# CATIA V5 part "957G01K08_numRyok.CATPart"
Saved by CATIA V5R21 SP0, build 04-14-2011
Part number: 957G01K08_numRyok
Bounding box of the stored display mesh (mm): x -33.75 to 33.05, y -126.3 to -25.1, z -8 to 12
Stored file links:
  C:\Users\ALI OZGUN\Desktop\alhan\957G01K08_numRyok.CATPart
  C:\Users\ALI OZGUN\Desktop\alhan\960B01P01.CATPart
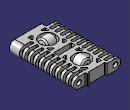
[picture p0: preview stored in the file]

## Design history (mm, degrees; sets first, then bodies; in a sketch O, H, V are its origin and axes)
Set1
  Plane1: type Normal, Curve Sketch12, RefPoint Sketch12.P3
  Point1: type Center, Curve edge [face of Pad1 from Sketch1.L2 | face of Pocket3 from Sketch4.A1]
  Line1: type PtDir, RefPoint Point1, Direction face of Pad1 from Sketch1.L2, Start 0, End 20
Set2
  Plane2: stored without definition
  Point2: stored without definition
  Line2: stored without definition
Body1 (main body)
  Sketch1 on zx-plane, origin (0, 0, 0), H (-1, 0, 0), V (0, 0, 1)
    construction line L1 (-25.05, 0) -> (25.75, 0)
    point P1 (-25.05, 0)
    line L2 (-25.05, 8) -> (25.75, 8)
    line L3 (25.75, -8) -> (-25.05, -8)
    arc A1 centre (25.75, 0) radius 8 from (25.75, 8) to (25.75, -8) cw
    arc A2 centre (-25.05, 0) radius 8 from (-25.05, -8) to (-25.05, 8) cw
    distance L1 L2 = 8
    distance P1 V = 25.05
    length L1 = 50.8
    coincidence: P1 H
    horizontal: L1 H
    tangency: A1 L2, A2 L2, A1 L3, A2 L3
  Pad1: profile Sketch1, direction (0, 1, 0), length 127.5, mirrored extent
  Sketch2 on face of Pad1 from Sketch1.L2, origin (0, 0, 8), H (1, 0, 0), V (0, 1, 0)
    line L1 (-50.9731, -119.3) -> (-16.75, -119.3)
    line L2 (-15.75, -120.3) -> (-15.75, -122.5)
    line L3 (-16.75, -123.5) -> (-50.9731, -123.5)
    line L4 (-50.9731, -123.5) -> (-50.9731, -119.3)
    arc A1 centre (-16.75, -120.3) radius 1 from (-16.75, -119.3) to (-15.75, -120.3) cw
    arc A2 centre (-16.75, -122.5) radius 1 from (-15.75, -122.5) to (-16.75, -123.5) cw
    reference projected line E1 (-25.75, -127.5) -> (25.05, -127.5) from edge [start face of Pad1 | face of Pad1 from Sketch1.L2]
    reference projected line E2 through (-25.75, 0) direction (0, 1) from axis of face of Pad1 from Sketch1.A1
    radius A1 = 1
    radius A2 = 1 {= Sketch2.radius(A1)}
    length L4 = 4.2
    distance L3 E1 = 4
    distance L2 E2 = 10
    horizontal: L1 H, L3 H
    vertical: L2 V, L4 V
    tangency: A1 L1, A1 L2, A2 L2, A2 L3
  Pocket1: profile Sketch2, direction (0, 0, -1), length 30, mirrored extent
  RectPattern1: of Pocket1, direction 1 instances 32, spacing 8.2, along axis of face of Pad1 from Sketch1.A1
  Sketch3 on face of Pad1 from Sketch1.L2, origin (0, 0, 8), H (1, 0, 0), V (0, 1, 0)
    line L1 (50.2731, -123.4) -> (50.2731, -127.6)
    line L2 (50.2731, -127.6) -> (16.05, -127.6)
    arc A1 centre (16.0504, -126.5996) radius 1.0004 from (16.05, -127.6) to (15.05, -126.6) cw
    line L3 (15.05, -126.6) -> (15.05, -124.4)
    arc A2 centre (16.0504, -124.4004) radius 1.0004 from (15.05, -124.4) to (16.05, -123.4) cw
    line L4 (16.05, -123.4) -> (50.2731, -123.4)
    reference projected line E2 through (25.05, 0) direction (0, 1) from axis of face of Pad1 from Sketch1.A2
    reference projected line E3 (-25.75, -127.5) -> (25.05, -127.5) from edge [start face of Pad1 | face of Pad1 from Sketch1.L2]
    distance L3 E2 = 10
    distance L4 E3 = 4.1
  Pocket2: profile Sketch3, direction (0, 0, -1), length 30
  RectPattern2: of Pocket2, direction 1 instances 32, spacing 8.2, along axis of face of Pad1 from Sketch1.A2
  RemoveFace1: RemoveFaces (face of RectPattern2; face of RectPattern2)
  RemoveFace2: RemoveFaces (face of RectPattern1; face of RectPattern1; face of Pad1 from Sketch1.A1)
  Sketch4 on face of Pad1 from Sketch1.L2, origin (0, 0, 8), H (1, 0, 0), V (0, 1, 0)
    circle A1 centre (0, -101.5) radius 12
    point P1 (0, -101.5)
    point P2 (-13, -84.5)
    line L1 (-12, -84.5) -> (-7.7574, -84.5)
    line L2 (13, -85.5) -> (13, -89.7426)
    line L3 (-7.7574, -118.5) -> (-12, -118.5)
    line L4 (-13, -117.5) -> (-13, -113.2574)
    point P3 (13, -84.5)
    point P4 (13, -118.5)
    point P5 (-13, -118.5)
    reference projected line E1 (-25.75, -127.5) -> (25.05, -127.5) from edge [start face of Pad1 | face of Pad1 from Sketch1.L2]
    line L5 (7.0503, -86.2071) -> (11.2929, -90.4497)
    line L6 (-7.0503, -86.2071) -> (-11.2929, -90.4497)
    line L7 (-11.2929, -112.5503) -> (-7.0503, -116.7929)
    line L8 (7.0503, -116.7929) -> (11.2929, -112.5503)
    arc A2 centre (12, -117.5) radius 1 from (12, -118.5) to (13, -117.5) ccw
    point P6 (12, -118.5)
    arc A3 centre (-12, -117.5) radius 1 from (-12, -118.5) to (-13, -117.5) cw
    arc A4 centre (-12, -85.5) radius 1 from (-12, -84.5) to (-13, -85.5) ccw
    arc A5 centre (12, -85.5) radius 1 from (12, -84.5) to (13, -85.5) cw
    line L9 (13, -113.2574) -> (13, -117.5)
    line L10 (7.7574, -84.5) -> (12, -84.5)
    line L11 (-13, -89.7426) -> (-13, -85.5)
    line L12 (12, -118.5) -> (7.7574, -118.5)
    arc A6 centre (12, -113.2574) radius 1 from (13, -113.2574) to (11.2929, -112.5503) ccw
    arc A7 centre (7.7574, -85.5) radius 1 from (7.7574, -84.5) to (7.0503, -86.2071) ccw
    arc A8 centre (12, -89.7426) radius 1 from (11.2929, -90.4497) to (13, -89.7426) ccw
    arc A9 centre (-7.7574, -85.5) radius 1 from (-7.7574, -84.5) to (-7.0503, -86.2071) cw
    arc A10 centre (-12, -89.7426) radius 1 from (-13, -89.7426) to (-11.2929, -90.4497) ccw
    arc A11 centre (-12, -113.2574) radius 1 from (-13, -113.2574) to (-11.2929, -112.5503) cw
    arc A12 centre (-7.7574, -117.5) radius 1 from (-7.0503, -116.7929) to (-7.7574, -118.5) cw
    arc A13 centre (7.7574, -117.5) radius 1 from (7.7574, -118.5) to (7.0503, -116.7929) cw
    point P42 (-13, -72.3)
    line L13 (-12, -72.3) -> (12, -72.3)
    line L14 (13, -73.3) -> (13, -78.3)
    line L15 (12, -79.3) -> (-12, -79.3)
    line L16 (-13, -78.3) -> (-13, -73.3)
    point P43 (13, -79.3)
    point P44 (-13, -79.3)
    arc A14 centre (-12, -73.3) radius 1 from (-12, -72.3) to (-13, -73.3) ccw
    point P45 (-12, -72.3)
    point P46 (-13, -73.3)
    arc A15 centre (12, -73.3) radius 1 from (12, -72.3) to (13, -73.3) cw
    point P48 (12, -72.3)
    point P49 (13, -73.3)
    arc A16 centre (12, -78.3) radius 1 from (13, -78.3) to (12, -79.3) cw
    point P51 (13, -78.3)
    point P52 (12, -79.3)
    arc A17 centre (-12, -78.3) radius 1 from (-12, -79.3) to (-13, -78.3) cw
    point P54 (-12, -79.3)
    point P55 (-13, -78.3)
    axis line L17 (15.2688, -101.5) -> (-36.2816, -101.5)
    point P59 (-13, -130.7)
    point P60 (13, -123.7)
    point P61 (-13, -123.7)
    point P62 (-12, -130.7)
    point P63 (-13, -129.7)
    point P65 (12, -130.7)
    point P66 (13, -129.7)
    point P68 (13, -124.7)
    point P69 (12, -123.7)
    point P71 (-12, -123.7)
    point P72 (-13, -124.7)
    line L18 (-12, -130.7) -> (12, -130.7)
    line L19 (13, -129.7) -> (13, -124.7)
    line L20 (12, -123.7) -> (-12, -123.7)
    line L21 (-13, -124.7) -> (-13, -129.7)
    arc A18 centre (-12, -129.7) radius 1 from (-12, -130.7) to (-13, -129.7) cw
    arc A19 centre (12, -129.7) radius 1 from (12, -130.7) to (13, -129.7) ccw
    arc A20 centre (12, -124.7) radius 1 from (13, -124.7) to (12, -123.7) ccw
    arc A21 centre (-12, -124.7) radius 1 from (-12, -123.7) to (-13, -124.7) ccw
    radius A1 = 12
    distance L1 L3 = 34
    distance L4 V = 13
    distance P1 L1 = 17
    distance L3 E1 = 9
    angle L5 L1 = 45
    angle L6 L1 = 45
    angle L7 L3 = 45
    angle L8 L3 = 135
    radius A2 = 1
    radius A3 = 1 {= Sketch4.radius(A2)}
    distance P2 P3 = 26
    radius A4 = 1 {= Sketch4.radius(A2)}
    radius A5 = 1 {= Sketch4.radius(A2)}
    distance L8 A2 = 5
    distance L7 A3 = 5
    distance L6 A4 = 5
    distance L5 A5 = 5
    radius A6 = 1
    radius A7 = 1 {= Sketch4.radius(A6)}
    radius A8 = 1 {= Sketch4.radius(A6)}
    radius A9 = 1 {= Sketch4.radius(A6)}
    radius A10 = 1 {= Sketch4.radius(A6)}
    radius A11 = 1 {= Sketch4.radius(A6)}
    radius A12 = 1 {= Sketch4.radius(A6)}
    radius A13 = 1 {= Sketch4.radius(A6)}
    distance L1 L15 = 5.2
    distance P44 P42 = 7
    radius A14 = 1
    radius A15 = 1 {= Sketch4.radius(A14)}
    radius A16 = 1 {= Sketch4.radius(A14)}
    radius A17 = 1 {= Sketch4.radius(A14)}
    coincidence: P1 V, L3 P4, L2 P4, L3 P5, L4 P5, L1 P2, L4 P2, L1 P3, L2 P3, L2 L9, L1 L10, L4 L11, P6 L3, P42 L4, P43 L2, L13 P42, L16 P42, L14 P43, L15 P43, L15 P44, L16 P44, L17 P1
    horizontal: L1 H, L3 H, L10 H, L13 H, L15 H, L17 H
    vertical: L2 V, L4 V, L9 V, L11 V, L14 V, L16 V
    tangency: A2 L3, A2 L2, A3 L3, A3 L4, A4 L1, A4 L4, A5 L1, A5 L2, L12 A2, A6 L9, A6 L8, A7 L10, A7 L5, A8 L5, A8 L2, A9 L1, A9 L6, A10 L11, A10 L6, A11 L4, A11 L7, A12 L7, A12 L3, A13 L12, A13 L8, A14 L13, A14 L16, A15 L13, A15 L14, A16 L14, A16 L15, A17 L15, A17 L16
    symmetry: P42 P59 L17, P43 P60 L17, P44 P61 L17, P45 P62 L17, P46 P63 L17, P48 P65 L17, P49 P66 L17, P51 P68 L17, P52 P69 L17, P54 P71 L17, P55 P72 L17, L13 L18 L17, L14 L19 L17, L15 L20 L17, L16 L21 L17, A14 A18 L17, A15 A19 L17, A16 A20 L17, A17 A21 L17
  Pocket3: profile Sketch4, direction (0, 0, -1), length 30
  RectPattern3: of Pocket3, direction 1 instances 5, spacing 51.4, along axis of face of Pad1 from Sketch1.A1
  RemoveFace3: RemoveFaces (face of Pocket3 from Sketch4.L19; face of Pocket3 from Sketch4.A20; face of Pocket3 from Sketch4.L20; face of Pocket3 from Sketch4.L21; face of Pocket3 from Sketch4.A21; face of Pocket2 from Sketch3.A1; face of Pocket2 from Sketch3.L3; face of Pocket2 from Sketch3.A2; face of Pocket2 from Sketch3.L4)
  Sketch5 on start face of Pad1, origin (0, -127.5, 0), H (1, 0, 0), V (0, 0, 1)
    projected line E3 (-15.75, 8) -> (-15.75, -8) from face of Pocket1 from Sketch2.L2
    projected line E4 (-15.75, 8) -> (-15.75, -8) from face of Pocket1 from Sketch2.L2
  Pad2: profile Sketch5, direction (0, -1, 0), length 12
  Sketch6 on zx-plane, origin (0, 0, 0), H (-1, 0, 0), V (0, 0, 1)
    circle A1 centre (25.75, 0) radius 3.5
    point P1 (25.75, 0)
    circle A2 centre (-25.05, 0) radius 3.5
    reference projected arc E1 centre (25.75, 0) radius 8 from (25.75, -8) to (25.75, 8) ccw from edge [face of RectPattern1 | face of Pad1 from Sketch1.A1]
    reference projected arc E2 centre (-25.05, 0) radius 8 from (-25.05, 8) to (-25.05, -8) ccw from edge [face of Pad1 from Sketch1.A2 | end face of Pad1]
    radius A2 = 3.5
    radius A1 = 3.5
    coincidence: P1 H
    concentricity: A1 E1, A2 E2
  Pocket4: profile Sketch6, direction (0, -1, 0), length 184, mirrored extent
  Sketch7 on face of Pad2 from Sketch5.E4, origin (-15.75, 0, 0), H (0, -1, 0), V (0, 0, 1)
    line L1 (131.394, 4.4412) -> (136.4149, 4.4412)
    line L2 (136.4149, 4.4412) -> (136.4149, -5.0929)
    line L3 (136.4149, -5.0929) -> (131.394, -5.0929)
    line L4 (131.394, -5.0929) -> (131.394, 4.4412)
    horizontal: L1 H, L3 H
    vertical: L2 V, L4 V
  Pocket5: profile Sketch7, direction (1, 0, 0), length 21
  Sketch8 on face of Pad2, origin (0, 0, -8), H (1, 0, 0), V (0, -1, 0)
    line L1 (0.8391, 137.9218) -> (7.819, 137.9218)
    line L2 (7.819, 137.9218) -> (7.819, 135.2061)
    line L3 (7.819, 135.2061) -> (0.8391, 135.2061)
    line L4 (0.8391, 135.2061) -> (0.8391, 137.9218)
    horizontal: L1 H, L3 H
    vertical: L2 V, L4 V
  Pocket6: profile Sketch8, direction (0, 0, 1), length 7
  Sketch9 on face of Pad2, origin (0, 0, -8), H (1, 0, 0), V (0, -1, 0)
    line L1 (-41.5561, 126.3) -> (43.6093, 126.3)
    line L2 (43.6093, 126.3) -> (43.6093, 25.1)
    line L3 (43.6093, 25.1) -> (-41.5561, 25.1)
    line L4 (-41.5561, 25.1) -> (-41.5561, 126.3)
    reference projected line E1 (-16.75, 25.1) -> (-25.75, 25.1) from edge [face of Pad1 from Sketch1.L3 | face of RectPattern1]
    length L2 = 101.2
    horizontal: L1 H, L3 H
    vertical: L2 V, L4 V
    coincidence: L3 E1
  Pocket7: profile Sketch9, direction (0, 0, 1), length 34, mirrored extent, outer side
  RemoveFace4: RemoveFaces (face of RectPattern2; face of RectPattern2; face of RectPattern2; face of RectPattern2; face of RectPattern2)
  RemoveFace5: RemoveFaces (face of Pocket1 from Sketch2.L3; face of Pad1 from Sketch1.A1; face of Pocket4 from Sketch6.A1; face of Pocket1 from Sketch2.A2)
  Sketch10 on face of Pocket1 from Sketch2.L2, origin (-15.75, 0, 0), H (0, -1, 0), V (0, 0, 1)
    line L1 (121.635, 5.0181) -> (124.8716, 5.0181)
    line L2 (124.8716, 5.0181) -> (124.8716, -4.4654)
    line L3 (124.8716, -4.4654) -> (121.635, -4.4654)
    line L4 (121.635, -4.4654) -> (121.635, 5.0181)
    horizontal: L1 H, L3 H
    vertical: L2 V, L4 V
  Pocket8: profile Sketch10, direction (1, 0, 0), length 26
  Sketch11 on face of Pad2, origin (0, 0, -8), H (1, 0, 0), V (0, -1, 0)
    point P1 (0, 124.8571)
    line L1 (0, 124.8571) -> (9.0453, 124.8571)
    line L2 (9.0453, 124.8571) -> (9.0453, 122.1462)
    line L3 (9.0453, 122.1462) -> (0, 122.1462)
    line L4 (0, 122.1462) -> (0, 124.8571)
    coincidence: P1 V
    horizontal: L1 H, L3 H
    vertical: L2 V, L4 V
  Pocket9: profile Sketch11, direction (0, 0, 1), length 10
Body2
  Solid1: linked copy from another document
  Translate1: Direction yz-plane, ToTransfor Solid1, Length 50.8
Body3
  Sketch12 on xy-plane, origin (0, 0, 0), H (1, 0, 0), V (0, 1, 0)
    point P1 (0, -101.5)
    reference projected circle E1 centre (0, -101.5) radius 12 from edge [face of Pad1 from Sketch1.L2 | face of Pocket3 from Sketch4.A1]
    line L1 (-12.5, -101.5) -> (12.5, -101.5)
    point P3 (12.5, -101.5)
    length L1 = 25
    distance P3 V = 12.5
    concentricity: P1 E1
    horizontal: L1 H
    coincidence: L1 P1
  Sketch13 on Plane1, origin (12.5, 0, 0), H (0, 1, 0), V (0, 0, 1)
    circle A1 centre (-101.5, 0) radius 1.5
    point P1 (-101.5, 0)
    reference projected point E1 (-101.5, 0) from Sketch12.P3
    radius A1 = 1.5
    coincidence: P1 E1
  Slot1: profile Sketch13, centre curve Sketch12
  Translate2: Direction xy-plane, ToTransfor Slot1, Length 4
  Rotate1: ToTransfor Translate2, Angle 0, Axis Line1
  RectPattern4: of the body so far, direction 1 instances 5, spacing 51.4, along axis of face of Pad1 from Sketch1.A2, deactivated
Body4
  Sketch14 on yz-plane, origin (0, 0, 0), H (0, 1, 0), V (0, 0, 1)
    circle A1 centre (-101.5, 4) radius 8
    circle A2 centre (-101.5, 3.7143) radius 1.75
    radius A1 = 8
    radius A2 = 1.75
  Pad3: profile Sketch14, direction (1, 0, 0), length 8, mirrored extent
  Fillet1: radius 2, on edge [face of Pad3 from Sketch14.A1 | end face of Pad3]; edge [start face of Pad3 | face of Pad3 from Sketch14.A1]
  Rotate2: ToTransfor Fillet1, Angle 0, Axis Line1
  RectPattern5: of the body so far, direction 1 instances 5, spacing 51.4, along axis of face of Pad1 from Sketch1.A2, deactivated
Body5
  Solid2: solid without history
  Pocket10: profile Sketch16, direction (0, 0, 1), length 27, opposite side length 43
  Sketch15 on xy-plane, origin (0, 0, 0), H (1, 0, 0), V (0, 1, 0)
Body6
  Solid3: solid without history
  Sketch16 on xy-plane, origin (0, 0, 0), H (1, 0, 0), V (0, 1, 0)
    line L1 (61.141, -26.3381) -> (-51.0359, -26.3381)
    line L2 (-51.0359, -26.3381) -> (-51.0359, 120.7423)
    line L3 (-51.0359, 120.7423) -> (61.141, 120.7423)
    line L4 (61.141, 120.7423) -> (61.141, -26.3381)
    line L5 (-54.2992, -79.4817) -> (38.9401, -79.4817)
    line L6 (38.9401, -79.4817) -> (38.9401, -125.5216)
    line L7 (38.9401, -125.5216) -> (-54.2992, -125.5216)
    line L8 (-54.2992, -125.5216) -> (-54.2992, -79.4817)
    horizontal: L1 H, L3 H, L5 H, L7 H
    vertical: L2 V, L4 V, L6 V, L8 V
  Pad4: profile Sketch16, direction (0, 0, 1), length 27, opposite side length 59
